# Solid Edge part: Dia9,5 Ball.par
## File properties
Title: Dia9,5 Ball
Author: Dan
Template: Normal.par
Last saved by: Dan
Revision: 5
Application: Solid Edge
Density: 0 kg/mm^3
Accuracy: 0.99
Document Number: P52-018
Project Name: Piston Pump P52
Material: steel
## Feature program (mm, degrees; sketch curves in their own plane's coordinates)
sketch for "unnamed RevolvedProtrusion 1" plane through (0, 0, 0) normal (0, 0, 1) x-axis (1, 0, 0)
  arc centre (0, 0) radius 4.75 from (-4.75, 0) to (4.75, 0) cw
revolve "unnamed RevolvedProtrusion 1" add finite 360 deg about sketch line (-4.75, 0) -> (4.75, 0)
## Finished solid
Body 1: solid body, 1 face, 0 edges, 0 vertices.
  Faces by surface: sphere 1
Spherical faces by radius (mm): R4.75 x1
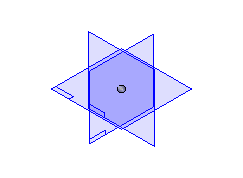
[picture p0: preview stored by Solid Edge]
